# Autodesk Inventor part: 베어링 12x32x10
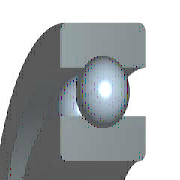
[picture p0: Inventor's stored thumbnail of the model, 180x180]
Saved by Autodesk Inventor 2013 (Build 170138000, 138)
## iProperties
IsCustomPart: 1
Created: 2012-02
Part Number: 베어링 12x32x10
Material: 강철, 연강
Description: 깊은 그루브 볼 베어링
Document SubType Name: Modeling
Standard: KS B 2023
Designer: test
Standards Organization: KS
Language: ko-KR
Size Designation: 6201 - 12 x 32 x 10
Categories: <MemberInstance><Categories><Category DisplayName="샤프트 부품" InternalName="7f7aeb1f-a693-4053-b835-cee3144e0d98" Mnemonic="SHFT"><Category DisplayName="베어링" Inter
Density: 1 g/cm^3
Author: test
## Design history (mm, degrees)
sketch "스케치" dims "d0" = 5.2 (= -0.26 x WD + 0.26 x BD)
  geometry: L1 (2.4, 11)-(7.6, 11); L2 (5, 11)-(5, 8.4); L3 (5, 11)-(5, 13.6); L4 (3.068, 9.26)-(0, 9.26); L5 (0, 6)-(10, 6); L6 (3.068, 12.74)-(0, 12.74); L7 (0, 16)-(10, 16); L8 (10, 6)-(10, 9.26); L9 (6.932, 9.26)-(10, 9.26); L10 (6.932, 12.74)-(10, 12.74); L11 (10, 16)-(10, 12.74); L12 (-1.4, 0)-(8.4, 0) reference; L13 (0, -0.3)-(0, 5.3) reference
  constraints: 22 end point, 4 point on line, 2 collinear, 2 perpendicular, 2 symmetric about line, 1 midpoint, 1 parallel, 14 other
  dimensions: "d9" = 12 diameter of L5 L12 (= WD); "d11" = 32 diameter of L7 L12 (= BD); "d12" = 10 distance between parallel lines of L8 L13 (= KB); "d13" = 18.52 diameter of L9 L12 (= 0.326 x BD + 0.674 x WD)
revolve "본체" stored, may be unused: angle "d6" = 90 deg
revolve "볼" stored, may be unused: angle "d7" = 90 deg
pattern_circular "IDS_ARRAYBALL[SIMPL:T]" dims angle "d3" = 360 deg
body "Solid1"
fillet "모깎기1" dims "d1" = 0.6 (= KRS)
other parameters: "WD" = 12 [user parameter; used in 5 equation terms], "BD" = 32 [user parameter; used in 5 equation terms], "KB" = 10 [user parameter; used in 1 equation term], "KRS" = 0.6 [user parameter; used in 1 equation term], "d4" = 0, "d5" = 0, "d8" = 0, "d14" = 0, "d15" = 0, "BBA" = 0 [user parameter], "BC0" = 3100000 [user parameter], "BC" = 6890000 [user parameter], "BR" = 16 (= 0.5 x BD) [user parameter], "WR" = 6 (= 0.5 x WD) [user parameter]
